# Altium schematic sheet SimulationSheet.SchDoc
size A; SheetNumber: 1; SheetTotal: 2
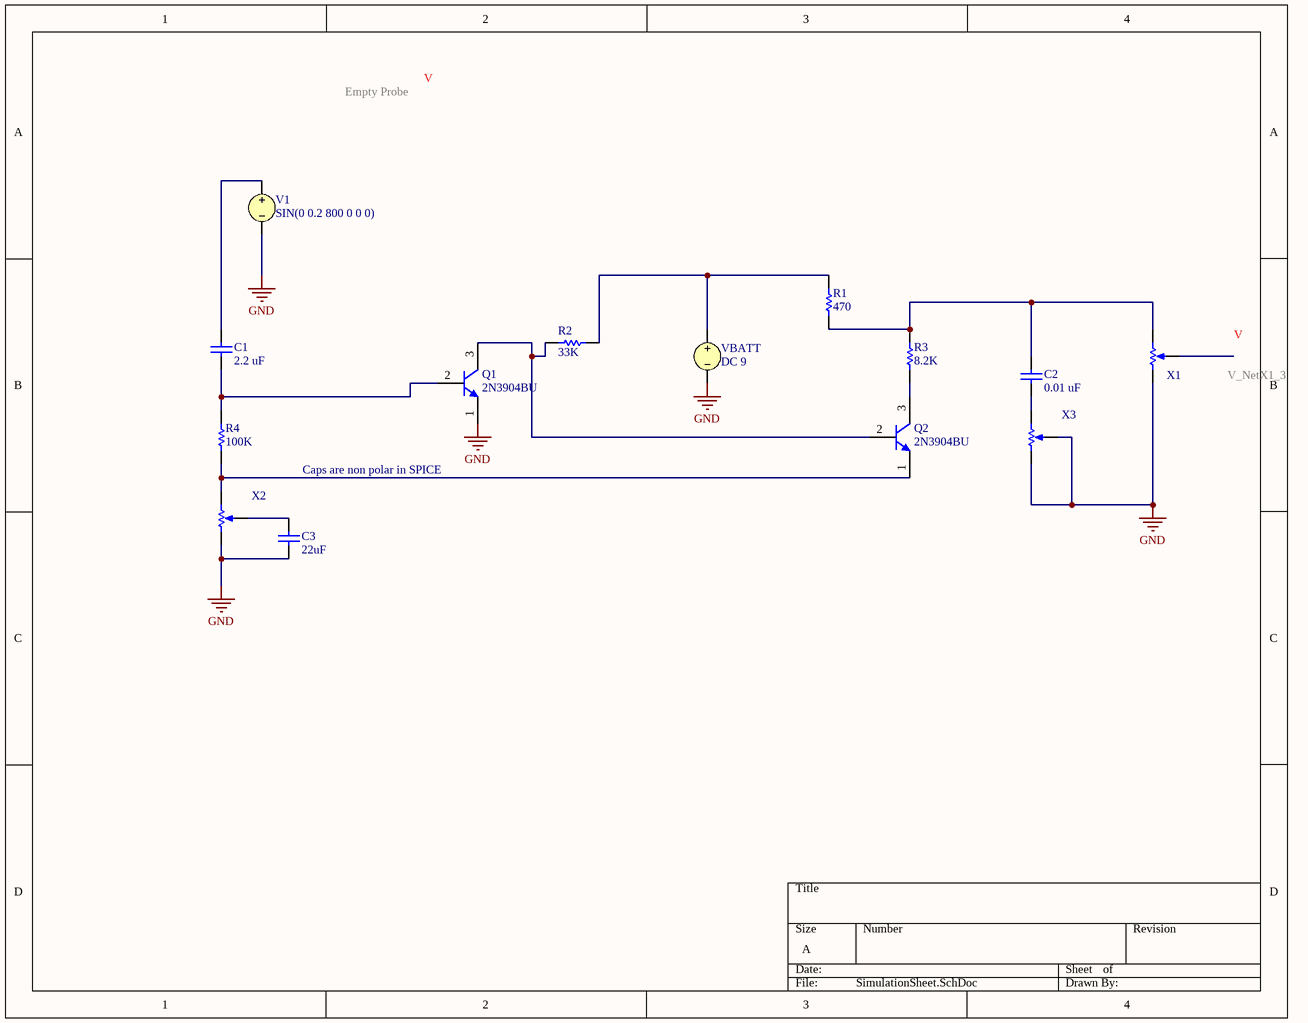
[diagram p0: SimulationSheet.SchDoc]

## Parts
C1  value 2.2 uF  (hidden comment: Capacitor)
C2  value 0.01 uF  (hidden comment: Capacitor)
C3  value 22uF  (hidden comment: Capacitor)
Q1  2N3904BU  [FAIR-TO-92]
Q2  2N3904BU  [FAIR-TO-92]
R1  value 470  (hidden comment: Resistor)
R2  value 33K  (hidden comment: Resistor)
R3  value 8.2K  (hidden comment: Resistor)
R4  value 100K  (hidden comment: Resistor)
V1  SIN(0 0.2 800 0 0 0)
VBATT  DC 9
X1  Potentiometer  (value not drawn)
X2  Potentiometer  (value not drawn)
X3  Potentiometer  (value not drawn)

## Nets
GND: C3.1 Q1.1(E) V1.2 VBATT.2 X1.1(TOP) X2.1(TOP) X3.1(TOP) X3.3(TAP)
NetC1_1: C1.1 Q1.2(B) R4.2
NetC1_2: C1.2 V1.1
NetC2_1: C2.1 X3.2(BOT)
NetC2_2: C2.2 R1.1 R3.1 X1.2(BOT)
NetC3_2: C3.2 X2.3(TAP)
NetQ1_3: Q1.3(C) Q2.2(B) R2.2
NetQ2_1: Q2.1(E) R4.1 X2.2(BOT)
NetQ2_3: Q2.3(C) R3.2
NetR1_2: R1.2 R2.1 VBATT.1

Not connected (* = marked no-connect by the designer): X1 3(TAP)

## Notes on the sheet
- Caps are non polar in SPICE

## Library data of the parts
C1-C3 = Capacitor: SimulationGenericComponent: True
Q1 Q2 = CMP-2000-04944-1: NPN General-Purpose Amplifier, 40 V VCEO, 0.2 A, -55 to 150 degC, 2-Pin TO-92, RoHS, Bulk; Manufacturer: FairchildSemiconductor; Maximum Collector Base Voltage: 60V; Minimum DC Current Gain: 40@0.1mA@1V; Maximum Collector Emitter Voltage: 40V; Maximum DC Collector Current: 0.2A; Rad Hard: No; Maximum Operating Frequency: 300(Min)MHz; Maximum Collector Emitter Saturation Voltage: 0.2@1mA@10mA; Maximum Power Dissipation: 625mW
R1-R4 = Resistor: TC1: 0; SimulationGenericComponent: True
V1 = VSRC: Voltage Source; Note: PCB Footprint - Not required; AC Magnitude: 1; AC Phase: 0; Carrier Frequency: 10Meg; Modulation Index: 5; Signal Frequency: 1Meg; Amplitude: 0.2; Frequency: 800
VBATT = VSRC: Voltage Source; Note: PCB Footprint - Not required; AC Magnitude: 1; AC Phase: 0; Value: 9
X1 X3 = Potentiometer: value: 500k; position: 0.1; SimulationGenericComponent: True
X2 = Potentiometer: value: 1k; position: 0.2; SimulationGenericComponent: True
